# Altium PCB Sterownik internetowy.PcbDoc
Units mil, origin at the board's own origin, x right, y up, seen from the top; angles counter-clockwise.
Board outline 6000 x 4000 mil, 2 copper layers (Top Layer, Bottom Layer); 75 components, 94 nets, 398 pads, 73 vias.
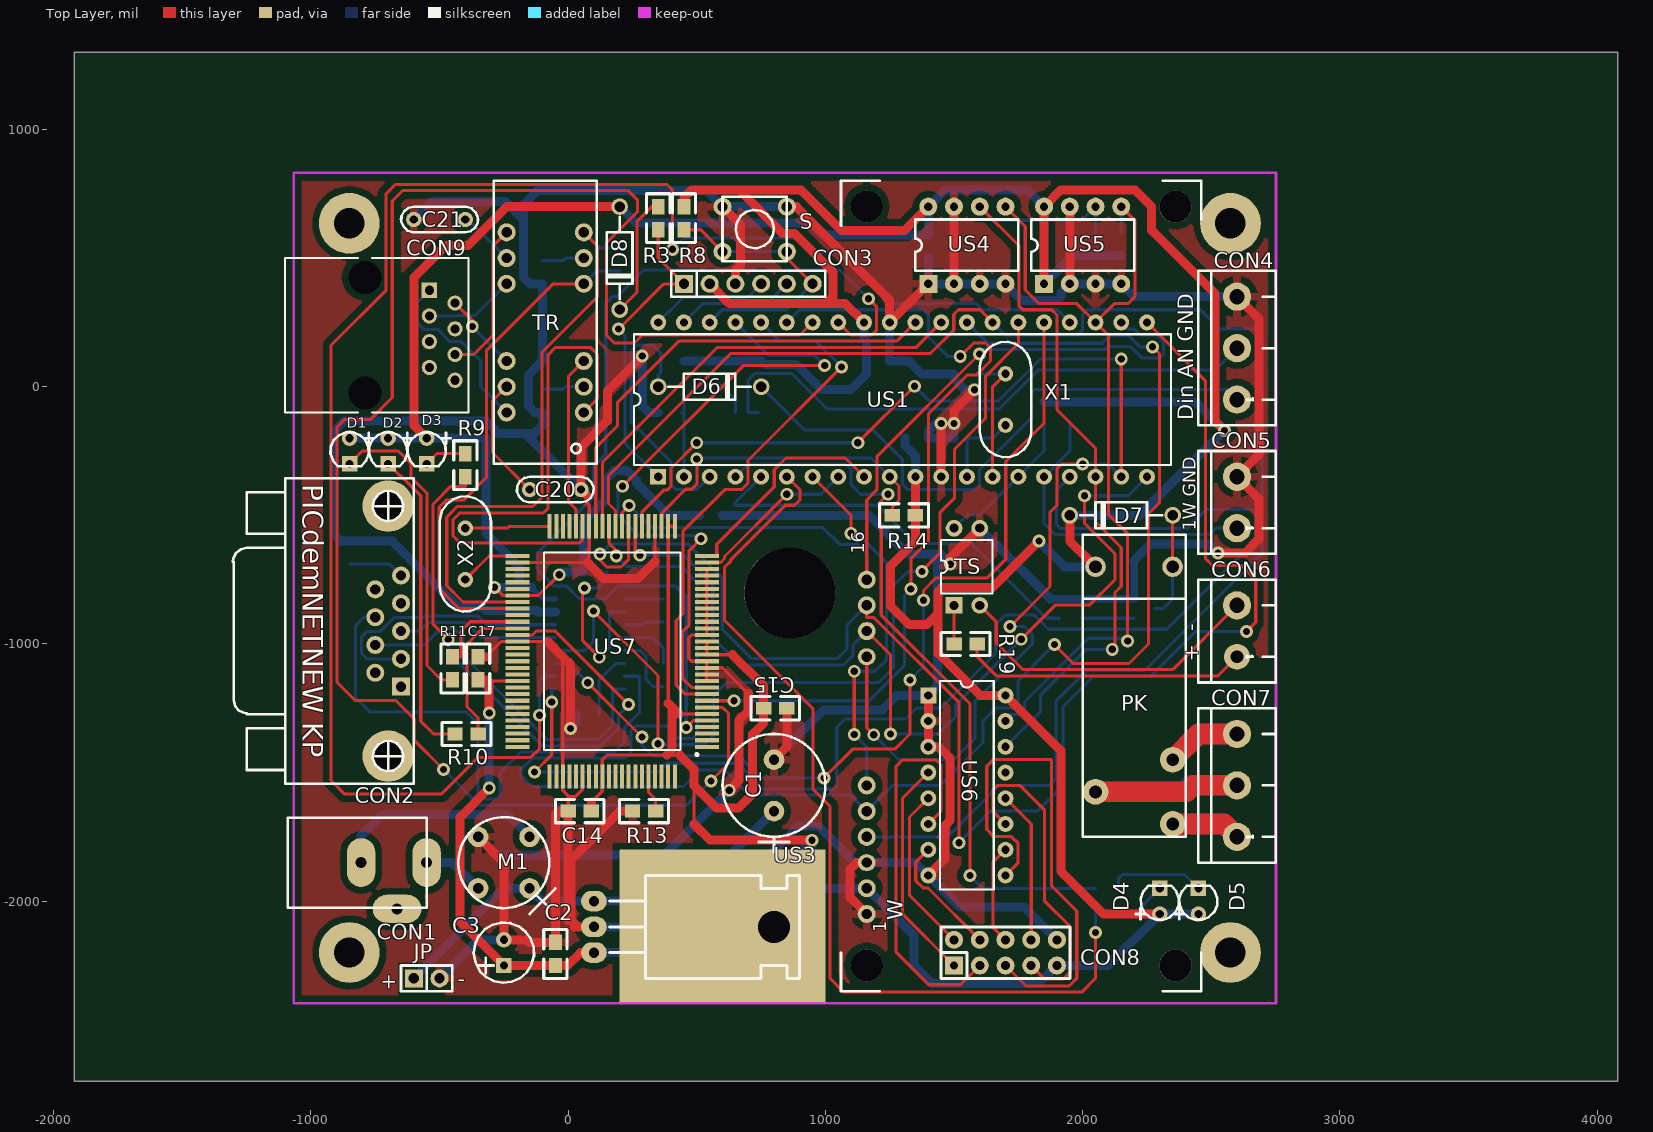
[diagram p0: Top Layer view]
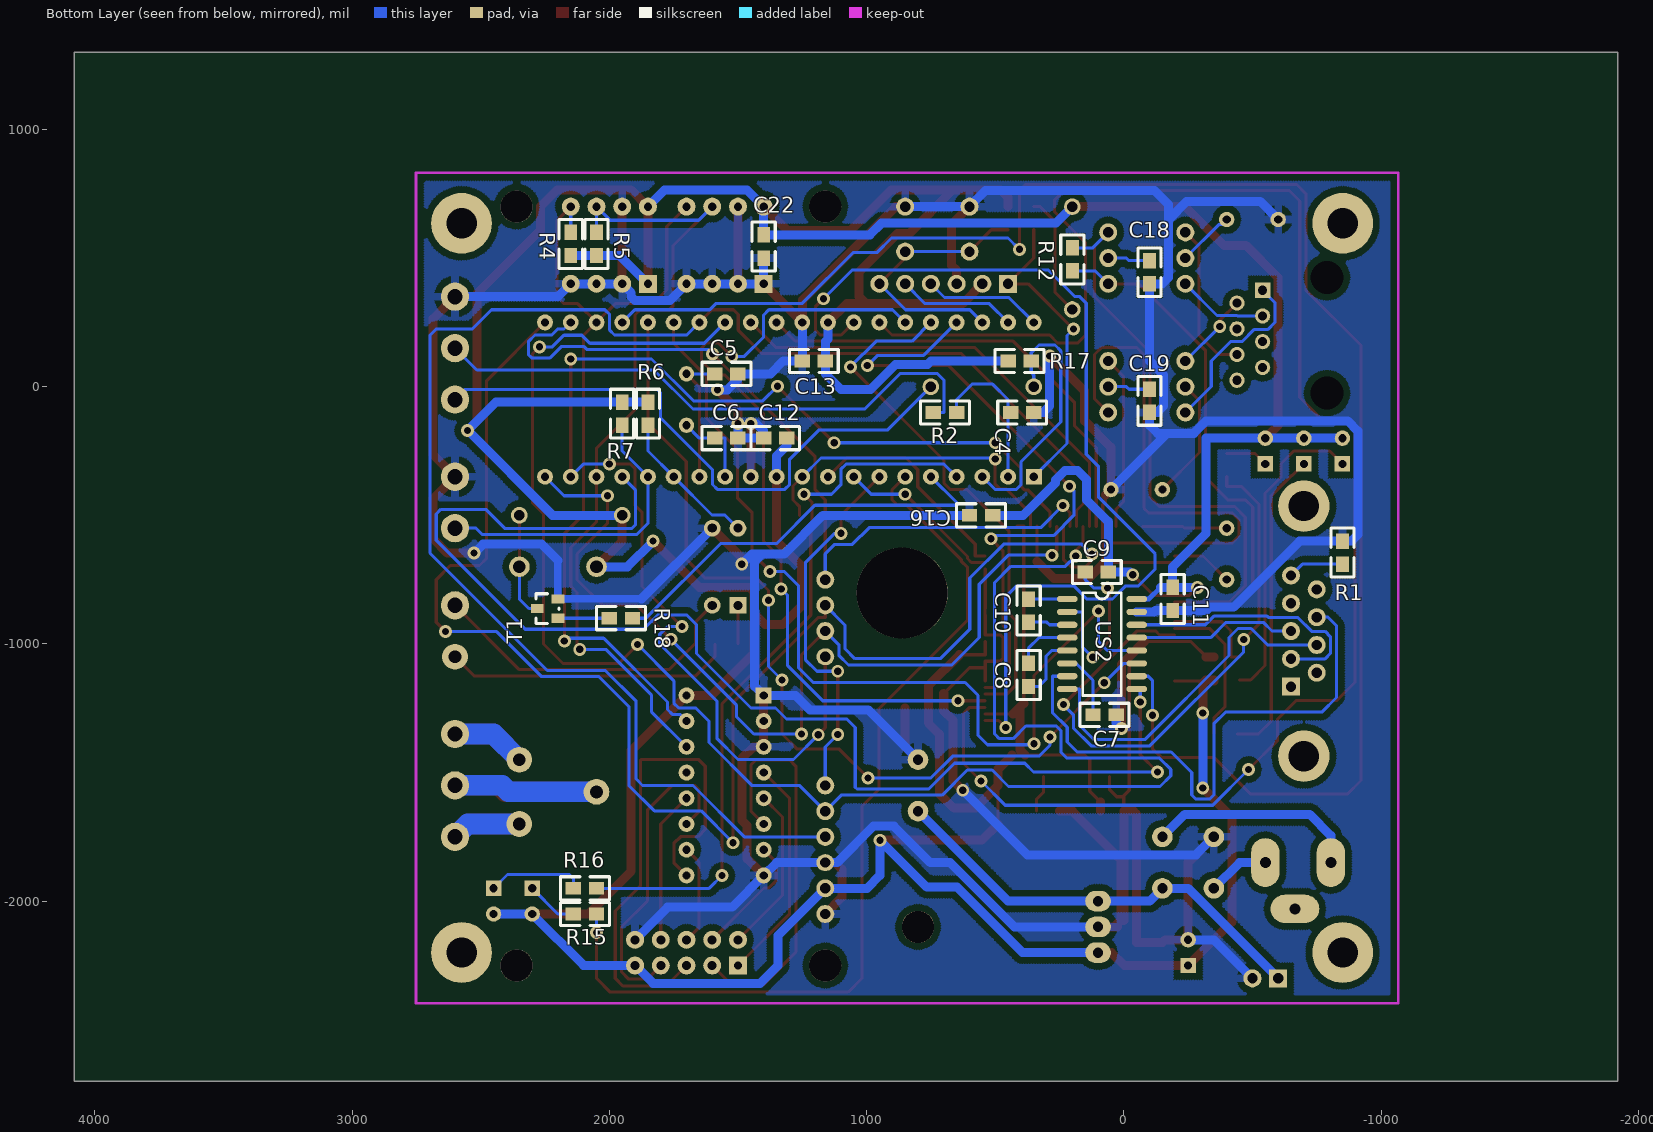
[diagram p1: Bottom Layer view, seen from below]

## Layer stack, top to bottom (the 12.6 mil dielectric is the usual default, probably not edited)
Top Layer: signal copper 1.4
Dielectric: dielectric 12.6, FR-4, Dk 4.8
Bottom Layer: signal copper 1.4

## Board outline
-1920,-2700 4080,-2700 4080,1300 -1920,1300

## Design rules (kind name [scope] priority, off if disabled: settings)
Clearance Clearance_3 [All] p1: gap=25
Clearance Clearance_1 [InComponent('US7')] p2 off: gap=8
Clearance Clearance_2 [InComponent('PK')] p3 off: gap=30
Clearance [All] p4 off: gap=12
ComponentClearance [All] p1: gap=10 collisioncheckmode=3 verticalgap=10
PolygonConnect [All] p1: connectstyle=Relief reliefconductorwidth=30 reliefentries=4 polygonreliefangle="90 Angle"
RoutingVias [All] p1: holewidth=28 width=50 viastyle="Through Hole" minholewidth=28 minwidth=50 maxholewidth=28 maxwidth=50
SMDNeckDown [All] p1: percent=80.000
SolderMaskExpansion [All] p1: expansion=4
TestPointUsage [All] p1: valid=0 allowmultiple=FALSE
Testpoint [All] p1: side=15 testpointundercomponent=TRUE minsize=40 maxsize=100 preferedsize=60 minholesize=0 maxholesize=40 preferedholesize=32 testpointgrid=1 style=1023 order=0123456789
Width Width_2 [InNet('NetCON7_3') Or InNet('NetCON7_1') Or InNet('NetCON7_2')] p1: maxlimit=90 minlimit=60 preferedwidth=80
Width Width_1 [InNet('VCC') Or InNet('GND')Or InNet('NetC1_1')Or InNet('NetCON1_1')Or InNet('NetCON1_2')] p2: maxlimit=35 minlimit=25 preferedwidth=35
Width [All] p3: maxlimit=12 minlimit=12 preferedwidth=12
17 further rules are at their usual default settings.

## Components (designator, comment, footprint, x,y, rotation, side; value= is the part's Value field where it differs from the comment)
C1 "470uF" CE10/5 800,-1650 r90 top
C2 "100nF" 0805 -50,-2250 r90 top
C3 "220uF" elektr1 -250,-2250 r180 top
C4 "100n" 0805 350,-100 r0 bottom
C5 "15p" 0805 1500,50 r0 bottom
C6 "15p" 0805 1500,-200 r0 bottom
C7 "1u" 0805 119.84,-1275.51 r180 bottom
C8 "1u" 0805 369.84,-1075.51 r270 bottom
C9 "1u" 0805 60,-720 r0 bottom
C10 "1u" 0805 369.84,-825.51 r270 bottom
C11 "1u" 0805 -190,-870 r90 bottom
C12 "100n" 0805 1400,-200 r180 bottom
C13 "100n" 0805 1250,100 r180 bottom
C14 "100N" 0805 0,-1650 r0 top
C15 "100N" 0805 850,-1250 r180 top
C16 "100N" 0805 600,-500 r180 bottom
C17 "100N" 0805 -350,-1050 r270 top
C18 "100N" 0805 -100,400 r90 bottom
C19 "100N" 0805 -100,-100 r90 bottom
C20 "100N" cap1 -50,-400 r180 top
C21 "100N" cap1 -500,650 r0 top
C22 "100N" 0805 1400,500 r90 bottom
CON1 "CON2" GNIAZDO-Z1 -550,-1850 r180 top
CON2 "DB9_zenskie" DB9Z -700,-950 r180 top
CON3 "Header 6" SIP-6 450,400 r0 top
CON4 "Header 3" con3-5 2600,150 r90 top locked
CON5 "Header 2" CON2-5#1 2600,-450 r270 top locked
CON6 "Header 2" CON2-5#2 2600,-950 r270 top locked
CON7 "Header 3" con3-5 2600,-1550 r90 top locked
CON8 "Header 10" IDC-10 1100,-1650 r0 top
CON9 "Header 8" JACK1.27-2H8B -1100,200 r270 top
D1 "LED0" led3 -850,-300 r0 top
D2 "LED0" led3 -700,-300 r0 top
D3 "LED0" led3 -550,-300 r0 top
D4 "LED0" led3 2300,-1950 r180 top
D5 "LED0" led3 2450,-1950 r180 top
D6 "BAT43" DIODa 550,0 r0 top
D7 "Diode 1N4007" DIODa 2150,-500 r180 top
D8 "Diode 1N4148" DIODa 200,500 r270 top
JP "CON2" sip2 -600,-2300 r0 top
M1 "" MOSTEK1 -350,-1750 r0 top
PK "RM96P-12" RM96P-12 2350,-700 r90 top
R1 "10" 0805 -850,-600 r270 bottom
R2 "2,2K" 0805 650,-100 r0 bottom
R3 "4,7K" 0805 350,700 r270 top
R4 "4,7K" 0805 2150,600 r270 bottom
R5 "4,7K" 0805 2050,600 r270 bottom
R6 "4,7K" 0805 1850,-150 r90 bottom
R7 "4,7K" 0805 1950,-150 r90 bottom
R8 "4,7K" 0805 450,700 r270 top
R9 "1K" 0805 -400,-350 r90 top
R10 "1K" 0805 -350,-1350 r180 top
R11 "1K" 0805 -450,-1050 r270 top
R12 "200R" 0805 200,450 r90 bottom
R13 "22K" 0805 250,-1650 r0 top
R14 "20K" 0805 1350,-500 r180 top
R15 "330R" 0805 2050,-2050 r0 bottom
R16 "330R" 0805 2050,-1950 r0 bottom
R17 "4,7K" 0805 450,100 r180 bottom
R18 "4,7K" 0805 2000,-900 r180 bottom
R19 "1K" 0805 1500,-1000 r0 top
S "SW-PB" key1 600,700 r270 top
T1 "NPN" sot-23 2200,-900 r90 bottom
TR "FL1012" fl1012 -289.37,-300 r90 top
TS "PC817" dip-4 1550,-700 r0 top
US1 "PIC18F452-E/P" PDIP600-40 1300,-50 r0 top
US2 "MAX232" so16 219.84,-825.51 r270 bottom
US3 "7805" TO-220 100,-2000 r270 top
US4 "AT24C256" DIP8 1400,400 r90 top
US5 "AT24C256" DIP8 1850,400 r90 top
US6 "PCF8574A" DIP-16 1550,-1550 r270 top
US7 "RTL8019AS" RTL8019 500,-1400 r90 top locked
W "LCD 16*1" LCDxxx 1160.63,-2050 r90 top locked
X1 "XTAL" XTAL 1700,-50 r270 top
X2 "20MHZ" XTAL -400,-650 r270 top

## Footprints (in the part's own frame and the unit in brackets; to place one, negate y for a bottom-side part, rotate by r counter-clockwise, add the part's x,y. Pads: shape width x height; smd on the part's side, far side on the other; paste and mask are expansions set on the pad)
0805 [mil]
  rect 60x50 smd: 1(0,0) 2(90,0)
  silkscreen extent -50,-45 140,45
cap1 [mil]
  round 60 hole 32: 1(-100,0) 2(100,0)
  silkscreen extent -150,-50 150,50
CE10/5 [mil]
  round 80 hole 40: 1(0,0) 2(200,0)
  silkscreen extent -160,-200 300,200
CON2-5#1 [mil]
  round 110 hole 60: 1(100,0) 2(-100,0)
  silkscreen extent -200,-150 200,150
CON2-5#2 [mil]
  round 100 hole 50: 1(100,0)
  round 110 hole 60: 2(-100,0)
  silkscreen extent -200,-150 200,150
con3-5 [mil]
  round 110 hole 60: 1(-200,0) 2(0,0) 3(200,0)
  silkscreen extent -300,-150 300,150
DB9Z [mil]
  rect 70x70 hole 40: 1(-50,216)
  round 70 hole 40: 2(-50,108) 3(-50,0) 4(-50,-108) 5(-50,-216) 6(50,162) 7(50,54) 8(50,-54) 9(50,-162)
  round 200 hole 118.11: 23(0,486) 26(0,-486)
  Bottom Layer lines w10: -52,221 -55,221
  silkscreen extent -100,-594 604,594
DIODa [mil]
  round 65 hole 40: 1(-200,0) 2(200,0)
  silkscreen extent -160,-50 160,50
DIP8 [mil]
  rect 70x70 hole 32: 1(0,0)
  round 70 hole 32: 2(0,-100) 3(0,-200) 4(0,-300) 5(300,-300) 6(300,-200) 7(300,-100) 8(300,0)
  silkscreen extent 50,-350 250,50
dip-4 [mil] "DIP; 4 Leads; Row Spacing 7.62 mm; Pitch 2.54 mm"
  rect 65x65 hole 35.43: 1(-50,-150)
  round 65 hole 35.43: 2(50,-150) 3(50,150) 4(-50,150)
  silkscreen extent -100,-104 100,104
DIP-16 [mil] "DIP; 16 Leads; Row Spacing 7.62 mm; Pitch 2.54 mm"
  rect 62x62 hole 32: 1(-350,-150)
  round 62 hole 32: 2(-250,-150) 3(-150,-150) 4(-50,-150) 5(50,-150) 6(150,-150) 7(250,-150) 8(350,-150) 9(350,150) 10(250,150) 11(150,150) 12(50,150) 13(-50,150) 14(-150,150) 15(-250,150) 16(-350,150)
  silkscreen extent -406,-104 406,104
elektr1 [mil]
  rect 60x60 hole 32: 1(0,0)
  round 60 hole 32: 2(0,-100)
  silkscreen extent -117,-167 118,67
fl1012 [mil]
  round 70 hole 40: 1(200,-350) 2(300,-350) 3(400,-350) 6(700,-350) 7(800,-350) 8(900,-350) 9(900,-50) 10(800,-50) 11(700,-50) 14(400,-50) 15(300,-50) 16(200,-50)
  silkscreen extent 0,-400 1100,0
GNIAZDO-Z1 [mil]
  oval 110x190 hole 43: 1(0,0) 2(255,0)
  oval 190x110 hole 43: 3(115,180)
  silkscreen extent 0,-175 540,175
IDC-10 [mil]
  rect 70x70 hole 32: 1(400,-600)
  round 70 hole 35: 2(400,-500) 3(500,-600) 4(500,-500) 5(600,-600) 6(600,-500) 7(700,-600) 8(700,-500) 9(800,-600) 10(800,-500)
  silkscreen extent 350,-650 850,-450
JACK1.27-2H8B [mm] "Connector; PCB Jack, Thru-Hole; 1-Port, 8 Positions, 8 Loaded; Unshielded without Lightpipes; Right Angle"
  rect 1.5x1.5 hole 0.9: 1(-4.445,14.23)
  round 1.5 hole 0.9: 2(-3.175,16.77) 3(-1.905,14.23) 4(-0.635,16.77) 5(0.635,14.23) 6(1.905,16.77) 7(3.175,14.23) 8(4.445,16.77)
  round 2.95 hole 3.25 unplated: MH1(-5.715,7.88) MH2(5.715,7.88)
  silkscreen extent -7.62,0 7.62,18.1
key1 [mil]
  round 70 hole 40: 1(0,250) 1(0,0) 2(175,250) 2(175,0)
  silkscreen extent -38,0 212,250
LCDxxx [mil]
  round 70 hole 40: 1(0,0) 2(100,0) 4(300,0) 5(400,0) 6(500,0) 12(1100,0) 13(1200,0) 14(1300,0)
  oval 65x70 hole 40: 3(200,0) 11(1000,0)
  round 125 hole 125: ""(-200,0) ""(-200,-1200) ""(2750,-1200) ""(2750,0)
  silkscreen extent -300,-1300 2850,100
led3 [mil]
  rect 60x60 hole 32: 1(0,0)
  round 60 hole 32: 2(0,100)
  silkscreen extent -74,-10 93,123
MOSTEK1 [mil]
  round 80 hole 40: 1(200,0) 2(200,-200) 3(0,-200) 4(0,0)
  silkscreen extent -77,-300 300,77
PDIP600-40 [mil] "DIP, Plastic; 40 Leads; Row Spacing 15.24 mm; Pitch 2.54 mm"
  rect 62x62 hole 32: 1(-950,-300)
  round 62 hole 32: 2(-850,-300) 3(-750,-300) 4(-650,-300) 5(-550,-300) 6(-450,-300) 7(-350,-300) 8(-250,-300) 9(-150,-300) 10(-50,-300) 11(50,-300) 12(150,-300) 13(250,-300) 14(350,-300) 15(450,-300) 16(550,-300) 17(650,-300) 18(750,-300) 19(850,-300) 20(950,-300) 21(950,300) 22(850,300) 23(750,300) 24(650,300) 25(550,300) 26(450,300) 27(350,300) 28(250,300) 29(150,300) 30(50,300) 31(-50,300) 32(-150,300) 33(-250,300) 34(-350,300) 35(-450,300) 36(-550,300) 37(-650,300) 38(-750,300) 39(-850,300) 40(-950,300)
  silkscreen extent -1043,-254 1043,254
RM96P-12 [mil]
  round 80 hole 50: 1(0,0) 2(0,300)
  round 100 hole 50: 3(-750,0) 4(-875,300) 5(-1000,0)
  silkscreen extent -1050,-50 125,350
RTL8019 [mm]
  rect 0.4x2.4 smd: 1(0,-1) 2(0.65,-1) 3(1.3,-1) 4(1.95,-1) 5(2.6,-1) 6(3.25,-1) 7(3.9,-1) 8(4.55,-1) 9(5.2,-1) 10(5.85,-1) 11(6.5,-1) 12(7.15,-1) 13(7.8,-1) 14(8.45,-1) 15(9.1,-1) 16(9.75,-1) 17(10.4,-1) 18(11.05,-1) 19(11.7,-1) 20(12.35,-1) 21(13,-1) 22(13.65,-1) 23(14.3,-1) 24(14.95,-1) 25(15.6,-1) 26(16.25,-1) 27(16.9,-1) 28(17.55,-1) 29(18.2,-1) 30(18.85,-1) 51(18.85,17.7) 52(18.2,17.7) 53(17.55,17.7) 54(16.9,17.7) 55(16.25,17.7) 56(15.6,17.7) 57(14.95,17.7) 58(14.3,17.7) 59(13.65,17.7) 60(13,17.7) 61(12.35,17.7) 62(11.7,17.7) 63(11.05,17.7) 64(10.4,17.7) 65(9.75,17.7) 66(9.1,17.7) 67(8.45,17.7) 68(7.8,17.7) 69(7.15,17.7) 70(6.5,17.7) 71(5.85,17.7) 72(5.2,17.7) 73(4.55,17.7) 74(3.9,17.7) 75(3.25,17.7) 76(2.6,17.7) 77(1.95,17.7) 78(1.3,17.7) 79(0.65,17.7) 80(0,17.7)
  rect 2.4x0.4 smd: 31(21.775,2.175) 32(21.775,2.825) 33(21.775,3.475) 34(21.775,4.125) 35(21.775,4.775) 36(21.775,5.425) 37(21.775,6.075) 38(21.775,6.725) 39(21.775,7.375) 40(21.775,8.025) 41(21.775,8.675) 42(21.775,9.325) 43(21.775,9.975) 44(21.775,10.625) 45(21.775,11.275) 46(21.775,11.925) 47(21.775,12.575) 48(21.775,13.225) 49(21.775,13.875) 50(21.775,14.525) 81(-2.925,14.525) 82(-2.925,13.875) 83(-2.925,13.225) 84(-2.925,12.575) 85(-2.925,11.925) 86(-2.925,11.275) 87(-2.925,10.625) 88(-2.925,9.975) 89(-2.925,9.325) 90(-2.925,8.675) 91(-2.925,8.025) 92(-2.925,7.375) 93(-2.925,6.725) 94(-2.925,6.075) 95(-2.925,5.425) 96(-2.925,4.775) 97(-2.925,4.125) 98(-2.925,3.475) 99(-2.925,2.825) 100(-2.925,2.175)
  silkscreen extent -0.89,-0.13 19.18,15.1
sip2 [mil]
  rect 70x70 hole 40: 1(0,0)
  round 70 hole 40: 2(100,0)
  silkscreen extent -50,-50 150,50
SIP-6 [mil]
  rect 70x70 hole 40: 1(0,0)
  round 70 hole 40: 2(100,0) 3(200,0) 4(300,0) 5(400,0) 6(500,0)
  silkscreen extent -50,-50 550,50
so16 [mil]
  oval 24x80 smd: 1(0,0) 2(50,0) 3(100,0) 4(150,0) 5(200,0) 6(250,0) 7(300,0) 8(350,0) 9(350,270) 10(300,270) 11(250,270) 12(200,270) 13(150,270) 14(100,270) 15(50,270) 16(0,270)
  silkscreen extent -25,60 375,210
sot-23 [mil]
  rect 36x50 smd: 1(0,0) 2(75,0) 3(38,80)
  silkscreen extent -20,-5 95,85
TO-220 [mil]
  oval 80x100 hole 40: 1(0,0) 2(100,0) 3(200,0)
  round 125 hole 125: ""(100,700)
  silkscreen extent -100,60 300,800
XTAL [mil]
  round 60 hole 32: 1(-100,0) 2(100,0)
  silkscreen extent -224,-100 224,100

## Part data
C1 C3: library part ELECTRO1, "Electrolytic Capacitor"
C2 C4 C7 C8 C9 C10 C11: library part CAP, "Capacitor"
C5 C6 C12 C13 C14 C15 C16 C17 C18 C19 C20 C21 C22: library part Cap, "Capacitor"
CON1: "Connector"
CON2: library part DB9
CON3: "Header, 6-Pin"
CON4: "Header, 3-Pin"
CON5: library part "Header 3", "Header, 3-Pin"
CON6: library part "Header 10", "Header, 10-Pin"
CON7: library part "Header 8", "Header, 8-Pin"
CON8: "Header, 10-Pin"
CON9: "Header, 8-Pin"
D1 D2 D3 D4 D5: "Typical INFRARED GaAs LED"
D6 D8: library part "Diode 1N4007", "1 Amp General Purpose Rectifier"
D7: "1 Amp General Purpose Rectifier"
M1: library part BRIDGE1, "Diode Bridge"
R1 R2 R3 R4 R5 R6 R7 R8 R9 R10 R11 R12 R13 R14 R15 R16 R17 R18 R19: library part Res2, "Resistor"
S: "Switch"
T1: "NPN Bipolar Transistor"
US1: "High Performance, Enhanced FLASH Microcontroller with 10-Bit A/D, 32K FLASH, 40-Pin PDIP, Standard Volt Range, Extended Temperature"
US3: library part STAB1
US4: library part AT24C64
US5: library part PCF8574A
US7: library part RTL8019
X1: "Crystal Oscillator"
X2: library part XTAL, "Crystal Oscillator"

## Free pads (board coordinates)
  round 236.22 hole 118.11: 0(-850.79,635.04) 1(-850.79,-2199.61) 2(2574.41,-2199.61) 3(2574.41,635.04)
  round 354.33 hole 354.33: 4(861.81,-801.97)
  rect 800x600 smd: 5(600,-2100)

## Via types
v1: diameter 50, hole 28, Top Layer to Bottom Layer, 73 vias

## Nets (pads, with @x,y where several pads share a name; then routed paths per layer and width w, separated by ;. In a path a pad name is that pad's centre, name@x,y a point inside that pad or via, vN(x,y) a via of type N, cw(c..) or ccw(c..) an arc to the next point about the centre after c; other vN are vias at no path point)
A0: US1.33 US7.5 | length 3845.4
  Top Layer w12: v1(459,-1325) 486.36,-1297.64 US7.5 ; US1.33 1099,201 1180,201 1199,220 1199,310.5 v1(1167.5,342)
  Bottom Layer w12: v1(459,-1325) 459,-817 416,-774 195.01,-774 144.01,-825 44.01,-825 -6.99,-774 -57,-774 -122,-709 -122,-650 98,-430 98,-311 146,-263 146,325 171,350 190,350 293,453 1056.5,453 v1(1167.5,342)
A1: US1.34 US7.7 | length 6549.4
  Top Layer w12: v1(-485,-1488) -598,-1375 -598,-1292 -670,-1220 -828,-1220 -898,-1150 -898,-156 -870,-128 -770,-128 -683.79,-41.79 -683.79,722.21 -644,762 233,762 270,725 270,681 149,560 149,200 178.9,170.1 257.5,170.1 288.4,201 901,201 US1.34 ; US7.7 599.46,-1246.46 623,-1270 623,-1465 v1(555,-1533)
  Bottom Layer w12: v1(-485,-1488) -346,-1627 461,-1627 v1(555,-1533)
A2: US1.35 US7.8 | length 3185.8
  Top Layer w12: US7.8 v1(644.11,-1220.87) ; v1(1332,-787) 1332,-669 1401,-600 1401,-105.05 1552.18,46.13 1588.13,46.13 1642,100 1642,150 1622,170 1576,170 v1(1524,118)
  Bottom Layer w12: v1(644.11,-1220.87) 1170.42,-1220.87 1307,-1084.29 1307,-812 v1(1332,-787) ; US1.35 899,299 1380,299 1401,278 1401,192 1475,118 v1(1524,118)
A3: US1.36 US7.9 | length 2060.5
  Top Layer w12: US7.9 455,-1195.28 420,-1160.28 420,-909 446,-883 446,-562.5 608.5,-400 674,-400 699,-375 699,-287 v1(1063,77)
  Bottom Layer w12: US1.36 823,177 963,177 v1(1063,77)
A4: US1.37 US7.10 | length 2560.1
  Top Layer w12: v1(211,-387) 680,82 v1(997,82) ; v1(516.5,-591) 470,-637.5 470,-927 444,-953 444,-1133.68 480,-1169.68 US7.10
  Bottom Layer w12: v1(211,-387) 194,-404 194,-500 273,-579 504.5,-579 v1(516.5,-591) ; US1.37 778,122 957,122 v1(997,82)
CTS: US1.24 US2.10 | length 6674
  Top Layer w12: v1(-111,-1277) -111,-1407 -145,-1441 -350,-1441 -492,-1583 -870,-1583 -922,-1531 -922,160.79 -707.79,375 -707.79,750 -671.79,786 384,786 406,764 v1(406,534)
  Bottom Layer w12: v1(-111,-1277) -111,-1141.51 -95,-1125.51 US2.10 ; v1(406,534) 450,578 903,578 960,521 1053,521 1250,324 1585,324 1610,299 1901,299 US1.24
GND: C1.2 C2.2 C3.2 C4.1 C5.1 C6.1 C7.2 C11.1 C12.1 C13.1 C14.1 C15.1 C16.1 C17.1 C18.1 C19.1 C20.1 C21.1 C22.1 CON3.3 CON4.3 CON5.2 CON8.10 JP.2 M1.4 R1.1 R13.1 S.1 T1.2 TS.3 US1.12 US1.31 US2.15 US3.2 US4.1 US4.2 US4.3 US4.4 US4.7 US5.2 US5.3 US5.4 US5.7 US6.1 US6.2 US6.3 US6.8 US7.11 US7.12 US7.13 US7.14 US7.18 US7.19 US7.20 US7.21 US7.22 US7.23 US7.24 US7.25 US7.26 US7.27 US7.28 US7.34 US7.44 US7.52 US7.64 US7.83 US7.86 W.1 W.3 | length 26011.5
  Top Layer w12.6: -320.45,-1050 -261,-990.55 US7.64 -80.12,-990.55 ; US7.52 75.46,-683.46 ; -20.67,-1050 -20.67,-1329 US7.83 -20.67,-1568.66 0,-1589.33 ; C14.1 0,-1589.33 ; US7.86 56.1,-1565.4 27.17,-1594.33 5,-1594.33 0,-1589.33 ; 71.69,-421.69 71.69,-448.35 81.69,-458.35 US7.44 81.69,-632 80,-633.69 80,-688 ; 337.6,-679.4 US7.34 ; US7.11 539,-1144.09 US7.12@539,-1118.5 ; US7.12 US7.12@539,-1118.5 ; US7.14 US7.14@539,-1067.32 ; US7.18 US7.18@539,-964.96 ; US7.19 US7.19@539,-939.37 ; US7.20 US7.20@539,-913.78 ; US7.23 US7.23@539,-837.01 ; US7.24 US7.24@539,-811.42 ; US7.25 US7.25@539,-785.83 ; US7.26 US7.26@539,-760.24 ; US7.27 US7.27@539,-734.65 ; US7.28 539,-709.06 US7.27@539,-734.65 ; 700,-1192.91 600,-1092.91 US7.13 US7.13@539,-1092.91 ; US7.12@539,-1118.5 US7.13@539,-1092.91 ; US7.13@539,-1092.91 US7.14@539,-1067.32 ; US7.14@539,-1067.32 480,-1067.32 468.3,-1055.62 468.3,-976.66 480,-964.96 US7.18@539,-964.96 ; US7.18@539,-964.96 US7.19@539,-939.37 ; US7.19@539,-939.37 US7.20@539,-913.78 ; US7.20@539,-913.78 539,-888.19 US7.21 US7.22 539,-862.6 US7.23@539,-837.01 ; US7.23@539,-837.01 US7.24@539,-811.42 ; US7.24@539,-811.42 US7.25@539,-785.83 ; US7.25@539,-785.83 US7.26@539,-760.24 ; US7.26@539,-760.24 US7.27@539,-734.65
  Top Layer w35: M1.4 -250,-1850 C3.2 -160,-2150 -150,-2160 C2.2 -50,-1662.5 -37.5,-1650 C14.1 0,-2075 11,-2075 ; C17.1 -320.45,-1050 ; -80.12,-990.55 -20.67,-1050 9,-1079.67 v1(9,-1329) ; 71.69,-421.69 C20.1 50,-235 152,-133 152,-17 v1(288,119) ; 75.46,-683.46 80,-688 138,-746 271,-746 337.6,-679.4 ; US3.2 25,-2100 30.5,-2094.5 11,-2075 ; R13.1 200,-1650 11,-1839 11,-2075 ; S.1@600,700 670,630 670,472 650,452 CON3.3 ; v1(626,-1569) 664,-1531 664,-1297.42 700,-1261.42 700,-1192.91 ; C1.2 850,-1400 C15.1 ; S.1@850,700 887.01,700 1250,337.01 US1.31 US4.1 ; W.1 1096,-1985.37 1096,-1875 1121,-1850 W.3 ; US6.8 1464.5,-1835.5 1464.5,-1706.12 1484.5,-1686.12 1484.5,-1445 1439.5,-1400 US6.3 US6.2 US6.1 ; US1.12 v1(1450,-143) ; v1(1485.05,-689.95) 1485.05,-664.95 TS.3 ; v1(1500,-143) 1500,-92 v1(1580,-12) ; US4.2 US4.7 ; US5.2 US5.7 ; v1(2526,-647) 2630,-647 2685,-592 2685,-435 CON5.2 2685,-265 2685,265 CON4.3
  Bottom Layer w28.8: 1875,-825 T1.2 2200,-675
  Bottom Layer w35: C21.1 -530,720 -244,720 -174,650 ; JP.2 -350,-2150 C3.2 ; M1.4 -280,-1820 375,-1820 v1(626,-1569) ; US2.15 -117.49,-875.51 -123,-870 C11.1 -321,-870 -334.5,-856.5 -427,-856.5 -683.5,-600 R1.1 -885,-600 -910,-575 -910,-173 -870,-133 -320,-133 -272,-181 -169,-181 ; v1(9,-1329) 29.84,-1308.16 C7.2 ; C20.1 -169,-181 ; US3.2 425,-2100 675,-1850 752,-1850 893.5,-1708.5 973.5,-1708.5 1115,-1850 W.3 1350,-1850 US6.8 1523,-2023 1773,-2023 CON8.10 ; v1(288,119) 288,-75 313,-100 C4.1 ; C16.1 1169.5,-500 1320.5,-651 1407.11,-651 ; C1.2 993.5,-1256.5 1220.12,-1256.5 1276.62,-1200 US6.1 1435.5,-1164.5 1435.5,-679.39 1407.11,-651 ; S.1@850,700 600,700 538,762 -120,762 -174,708 -174,650 ; US1.31 C13.1 1323,100 1373,50 C5.1 1500,29 1541,-12 v1(1580,-12) ; C22.1 US4.1 US4.2 US4.3 US4.4 1765,335 1900,335 1915,350 1915,365 US5.2 US5.3 US5.4 2200,350 CON4.3 ; v1(1450,-143) 1430,-143 1400,-173 C12.1 C6.1 v1(1500,-143) ; v1(1485.05,-689.95) 1446.11,-651 1407.11,-651 ; TS.3 1875,-825 ; 2200,-675 2263,-612 2491,-612 v1(2526,-647) ; -174,650 -174,425 -149,400 C18.1 -100,100 -155,45 -155,-75 -130,-100 C19.1 -100,-150 -131,-181 -169,-181
MCLR: CON3.1 R3.2 US1.1 | length 1216.1
  Top Layer w12: v1(196,224) 372,400 CON3.1 350,500 R3.2
  Bottom Layer w12: v1(196,224) 221,199 221,-221 US1.1
NetC1_1: C1.1 JP.1 M1.2 US3.1 | length 1710.7
  Bottom Layer w35: JP.1 -250,-1950 M1.2 -100,-2000 US3.1 450,-2000 C1.1
NetC4_2: C4.2 R2.1 US1.2 | length 609.7
  Bottom Layer w12: C4.2 C4.2@450,-100 ; US1.2 C4.2@450,-100 ; R2.1 650,-50 590,10 550,10 510,10 450,-50 C4.2@450,-100
NetC5_2: C5.2 US1.14 X1.1 | length 530.7
  Top Layer w12: US1.14 1650,0 X1.1
  Bottom Layer w12: C5.2 X1.1
NetC6_2: C6.2 US1.13 X1.2 | length 320.7
  Bottom Layer w12: US1.13 1550,-200 C6.2 1650,-200 X1.2
NetC7_1: C7.1 US2.6 | length 261.3
  Bottom Layer w12: C7.1 119.84,-1141.51 185.84,-1075.51 US2.6
NetC8_1: C8.1 US2.4 | length 226.7
  Bottom Layer w12: US2.4 330,-975.51 369.84,-1015.35 C8.1
NetC8_2: C8.2 US2.5 | length 260.7
  Bottom Layer w12: US2.5 280,-1025.51 303,-1048.51 303,-1138.51 330,-1165.51 C8.2
NetC9_2: C9.2 US2.2 | length 682.8
  Top Layer w12: v1(63,-782) 55,-790 55,-986 v1(121,-1052)
  Bottom Layer w12: v1(63,-782) 118,-782 150,-750 C9.2 ; v1(121,-1052) 161,-1012 161,-875.51 US2.2
NetC10_1: C10.1 US2.1 | length 150
  Bottom Layer w12: US2.1 C10.1
NetC10_2: C10.2 US2.3 | length 154.1
  Bottom Layer w12: US2.3 289,-925.51 299,-915.51 C10.2
NetC18_2: C18.2 TR.7 | length 164.8
  Bottom Layer w12: C18.2 -20,490 -10,500 TR.7
NetC19_2: C19.2 TR.2 | length 164.8
  Bottom Layer w12: C19.2 -20,-10 -10,0 TR.2
NetC20_2: C20.2 TR.15 | length 482.3
  Top Layer w12: TR.15 -294,-54.63 -294,-256 C20.2
NetC21_2: C21.2 TR.10 | length 233.9
  Bottom Layer w12: C21.2 -400,631 -370.37,631 TR.10
NetCON1_1: CON1.1 M1.3 | length 241.4
  Bottom Layer w35: CON1.1 -450,-1850 M1.3
NetCON1_2: CON1.2 M1.1 | length 830.4
  Bottom Layer w35: CON1.2 -805,-1745 -722.5,-1662.5 -237.5,-1662.5 M1.1
NetCON2_2: CON2.2 US2.14 | length 1027.1
  Bottom Layer w12: CON2.2 -782.5,-1058 -803,-1037.5 -803,-971.5 -782.5,-951 -730.05,-951 -676.05,-897 -562.13,-897 -557.13,-892 -350,-892 -316.49,-925.51 US2.14
NetCON2_3: CON2.3 US2.13 | length 638.6
  Bottom Layer w12: CON2.3 -576.14,-950 -542.14,-916 -397,-916 -337.49,-975.51 US2.13
NetCON2_5: CON2.5 R1.2 | length 218.2
  Bottom Layer w12: R1.2 -694,-690 CON2.5
NetCON2_7: CON2.7 US2.8 | length 1380
  Bottom Layer w12: CON2.7 -559,-1004 -495,-940 -444,-940 -409,-975 -409,-1045 -82,-1372 116,-1372 172,-1316 172,-1175.51 US2.8
NetCON2_8: CON2.8 US2.7 | length 2223.7
  Bottom Layer w12: CON2.8 -794,-896 -827,-929 -827,-1208 -770,-1265 -395,-1265 -350,-1310 -350,-1587.5 -334.5,-1603 -279.5,-1603 -264,-1587.5 -264,-1500 -184,-1420 180.92,-1420 220,-1380.92 220,-1324.22 278,-1266.22 278,-1125.51 US2.7
NetCON4_1: CON4.1 D6.2 | length 2340.2
  Bottom Layer w12: D6.2 917.6,-167.6 1184.6,-167.6 1299,-282 1299,-380.5 1317.5,-399 1580,-399 1599,-380 1599,-323 1800.43,-121.57 1800.43,-25 1814.89,-10.54 2560.54,-10.54 CON4.1
NetCON4_2: CON4.2 R2.2 | length 2233.1
  Bottom Layer w12: R2.2 699,-100 699,25 725,51 869,51 1007,-87 1675,-87 1827,65 2515,65 CON4.2
NetCON5_1: CON5.1 R7.1 US1.16 | length 1200.6
  Bottom Layer w12: R7.1 1950,-250 US1.16 1850,-531 1893.5,-574.5 2494,-574.5 2518.5,-550 CON5.1
NetCON6_1: CON6.1 R19.2 | length 1121.3
  Top Layer w12: R19.2 1590,-1050 1664,-1124 2526,-1124 CON6.1
NetCON6_2: CON6.2 TS.2 | length 1255.2
  Top Layer w12: TS.2 1664.26,-914.26 1664.26,-996.35 1767.9,-1100 2350,-1100 CON6.2
NetCON7_1: CON7.1 PK.5 | length 541.4
  Top Layer w80: PK.5 2550,-1700 CON7.1
  Bottom Layer w80: PK.5 2550,-1700 CON7.1
NetCON7_2: CON7.2 PK.4 | length 1120.7
  Top Layer w80: PK.4 2405,-1575 2430,-1550 CON7.2
  Bottom Layer w80: PK.4 2392,-1575 2417,-1550 CON7.2
NetCON7_3: CON7.3 PK.3 | length 582.8
  Top Layer w80: PK.3 2450,-1350 CON7.3
  Bottom Layer w80: PK.3 2450,-1350 CON7.3
NetCON8_1: CON8.1 US6.4 | length 875
  Top Layer w12: US6.4 1299.13,-1600.87 1299.13,-2049.13 CON8.1
NetCON8_2: CON8.2 US6.5 | length 651.9
  Top Layer w12: US6.5 1327,-1673 1327,-1977 CON8.2
NetCON8_3: CON8.3 US6.6 | length 1573.8
  Top Layer w12: US6.6 1449,-1651 1449,-1470 1430,-1451 1299,-1451 1275,-1475 1275,-2198 1402,-2325 1525,-2325 CON8.3
NetCON8_4: CON8.4 US6.7 | length 484.7
  Top Layer w12: US6.7 1351,-1849 1351,-1920.3 1379.7,-1949 1399,-1949 CON8.4
NetCON8_5: CON8.5 US6.9 | length 2009.6
  Top Layer w12: CON8.5 1779.46,-2329.46 1947.54,-2329.46 1977,-2300 1977,-2038 1879,-1940 1879,-1452 1877,-1450 1652,-1450 1627,-1475 1627,-1721 1655,-1749 1723,-1749 1749,-1775 1749,-1851 US6.9
NetCON8_6: CON8.6 US6.10 | length 390.6
  Top Layer w12: CON8.6 1651,-2101 1651,-1849 US6.10
NetCON8_7: CON8.7 US6.11 | length 1258
  Top Layer w12: US6.11 1651,-1651 1651,-1567.5 1667.5,-1551 1758,-1551 1851,-1644 1851,-1998 1953,-2100 1953,-2275 1925,-2303 1853,-2303 CON8.7
NetCON8_8: CON8.8 US6.12 | length 591.4
  Top Layer w12: US6.12 1800,-1700 CON8.8
NetCON9_1: CON9.1 TR.16 | length 696.8
  Bottom Layer w12: CON9.1 -588,326.76 -588,250 -561,223 -507.5,223 -459.5,175 -415,175 -340,100 -340,0.63 TR.16
NetCON9_2: CON9.2 TR.14 | length 308
  Top Layer w12: CON9.2 -373,258.24 v1(-373,233.63)
  Bottom Layer w12: v1(-373,233.63) TR.14
NetCON9_3: CON9.3 TR.11 | length 352.2
  Bottom Layer w12: CON9.3 -442,275 -440,277 -362.37,277 TR.11
NetCON9_6: CON9.6 TR.9 | length 600.6
  Top Layer w12: CON9.6 -367,125 -293,199 -293,546.37 TR.9
NetD1_2: D1.1 R11.2 | length 1212.2
  Top Layer w12: D1.1 -800,-250 -661.11,-250 -611.11,-300 -611.11,-352.07 -549.19,-413.99 -549.19,-1083.81 -493,-1140 R11.2
NetD2_2: D2.1 R10.2 | length 1208.1
  Top Layer w12: D2.1 -654,-346 -651.12,-346 -573.19,-423.93 -573.19,-1300 -523.19,-1350 R10.2
NetD3_2: D3.1 R9.2 | length 166.6
  Top Layer w12: D3.1 -510,-260 R9.2
NetD4_2: D4.1 R15.2 | length 201.4
  Bottom Layer w12: R15.2 2200,-2050 D4.1
NetD5_2: D5.1 R16.2 | length 377.6
  Bottom Layer w12: R16.2 2140,-1911 2155,-1896 2396,-1896 D5.1
NetD6_1: D6.1 R17.2 US1.3 | length 1035.6
  Bottom Layer w12: D6.1 350,45 360,55 R17.2 360,132 330,162 267.5,162 245,139.5 245,-137 400,-292 400,-381.5 417.5,-399 501,-399 US1.3
NetD7_1: D7.1 PK.1 T1.3 | length 410.3
  Top Layer w12: PK.1 D7.1
  Bottom Layer w12: T1.3 2313,-862 2350,-825 PK.1
NetD8_2: D8.2 R3.1 | length 476.9
  Top Layer w12: D8.2 268,368 268,643.15 324.85,700 R3.1
NetR6_1: R6.1 TS.4 US1.15 | length 574.3
  Bottom Layer w12: TS.4 1551,-499 1601,-499 US1.15 1850,-250 R6.1
NetR9_1: R9.1 US7.63 | length 2296.9
  Top Layer w12: v1(-466,-983) -525.19,-923.81 -525.19,-456.19 -456.5,-387.5 -400,-387.5 R9.1 ; US7.63 -138.96,-964.96 -123,-949 -52,-949 v1(235,-1236)
  Bottom Layer w12: v1(-466,-983) -466,-1031.23 -101.23,-1396 127,-1396 196,-1327 196,-1275 v1(235,-1236)
NetR10_1: R10.1 US7.62 | length 589.1
  Top Layer w12: R10.1 -350,-1288 -393,-1245 -393,-1000 -332.37,-939.37 US7.62
NetR11_1: R11.1 US7.61 | length 368.2
  Top Layer w12: R11.1 -417,-1050 -417,-950 -380.78,-913.78 US7.61
NetR12_1: R12.1 TR.6 US7.59 | length 2024.3
  Top Layer w12: US7.59 -424.4,-862.6 -501.19,-785.81 -501.19,-467.97 -474.25,-441.03 -405.94,-441.03 -318,-353.09 -318,140 -58,400 TR.6
  Bottom Layer w12: TR.6 110.63,450 R12.1
NetR12_2: R12.2 TR.8 US7.58 | length 2275.9
  Top Layer w12: US7.58 -408.99,-837.01 -472,-774 -472,-507.09 -430.91,-466 -138,-466 -102,-430 -102,134 114,350 114,546.63 TR.8
  Bottom Layer w12: TR.8 120.63,540 R12.2
NetR13_2: R13.2 US7.96 | length 146.4
  Top Layer w12: US7.96 312.01,-1577 340,-1604.99 R13.2
NetR14_2: R14.2 US1.10 US7.33 | length 1289.9
  Top Layer w12: US7.33 363.19,-491.55 455.96,-398.78 480.35,-398.78 500,-379.13 v1(500,-281.51) ; US1.10 1286,-386 1286,-440.46 1260,-466.46 R14.2
  Bottom Layer w12: v1(500,-281.51) 504.51,-277 1177,-277 US1.10
NetR15_1: R15.1 US1.6 | length 3611
  Top Layer w12: US1.6 901,-401 901,-440 880,-461 843.26,-461 632,-672.26 632,-677.94 607,-702.94 607,-907 951,-1251 951,-1564 1018,-1631 1018,-2300 1071.46,-2353.46 1996.54,-2353.46 2050,-2300 v1(2050,-2122)
  Bottom Layer w12: v1(2050,-2122) R15.1
NetR16_1: R16.1 US1.4 | length 2845.7
  Top Layer w12: v1(1243,-418) 1212,-449 1212,-543 1217,-548 1217,-888 1562,-1233 v1(1562,-1900)
  Bottom Layer w12: US1.4 699,-301 1080,-301 1100,-321 1100,-381.5 1136.5,-418 v1(1243,-418) ; v1(1562,-1900) 1612,-1950 R16.1
NetR18_1: R18.1 T1.1 | length 200
  Bottom Layer w12: R18.1 T1.1
NetR18_2: R18.2 US1.5 | length 1597.1
  Bottom Layer w12: US1.5 648,-452 648,-461 1201,-461 1350,-610 1568,-610 1858,-900 R18.2
NetR19_1: R19.1 TS.1 | length 150
  Top Layer w12: R19.1 TS.1
NetTR_1: TR.1 US7.45 | length 2082.8
  Top Layer w12: US7.45 56.1,-594.4 42.5,-608 -420,-608 -448,-580 -448,-517.03 -421.99,-491.02 -97.02,-491.02 -78,-472 -78,124 -49,153 85.63,153 113.63,125 113.63,-47 TR.1
NetTR_3: TR.3 US7.46 | length 678.8
  Top Layer w12: US7.46 30.51,-476.51 2,-448 2,41.37 TR.3
NetUS1_7: US1.7 W.6 | length 1453.7
  Top Layer w12: US1.7 1099,-499 v1(1099,-570) ; v1(1112,-1352) v1(1112,-1106.03)
  Bottom Layer w12: v1(1099,-570) 1124,-570 1238,-684 1238,-1061 1192.97,-1106.03 v1(1112,-1106.03) ; v1(1112,-1352) 1160.63,-1400.63 W.6
NetUS1_8: US1.8 US7.29 | length 653.4
  Top Layer w12: US7.29 592.54,-683.46 608,-668 608,-660 v1(850,-418)
  Bottom Layer w12: v1(850,-418) 982,-418 US1.8
NetUS1_9: US1.9 US7.30 | length 863.9
  Top Layer w12: US7.30 577.59,-657.87 577.59,-612.3 801,-388.89 801,-323 847,-277 1077,-277 US1.9
NetUS1_19: US1.19 US7.36 W.11 | length 5055
  Top Layer w12: US7.36 286.42,-487.5 373.12,-400.8 386.7,-400.8 400,-387.5 400,-318 v1(500,-218) ; v1(1126,-218) v1(1346,2) ; W.11 1160.63,-1325.63 v1(1188,-1353) ; v1(1718,-932) 1873,-777 1873,-488 1901,-460 1901,-317.5 1917.5,-301 v1(2000,-301) ; US1.19 v1(2150,108)
  Bottom Layer w12: v1(500,-218) v1(1126,-218) ; v1(1188,-1353) 1284,-1449 1500,-1449 1582,-1367 1582,-1222 1804,-1000 1804,-962.5 1773.5,-932 v1(1718,-932) ; v1(1346,2) 1403,-55 1673,-55 1836,108 v1(2150,108) ; v1(2000,-301) 2101,-301 US1.19
NetUS1_20: US1.20 US7.37 W.12 | length 3613.6
  Top Layer w12: US7.37 260.83,-636.83 v1(279,-655) ; W.12 1253,-1042.37 v1(1253,-1350) ; v1(1761,-982) 1895,-848 2028,-848 2126,-750 2126,-650 2007,-531 v1(2007,-424)
  Bottom Layer w12: v1(279,-655) 449,-655 562,-768 562,-975 669,-1082 1070,-1082 1107.63,-1044.37 1107.63,-1003 W.12 ; v1(1253,-1350) 1438,-1350 1506.13,-1281.87 1506.13,-1236.87 v1(1761,-982) ; v1(2007,-424) 2176,-424 US1.20
NetUS1_21: US1.21 US7.38 W.13 | length 5964.1
  Top Layer w12: v1(124,-651) 124,-675 150,-701 205,-701 235.24,-670.76 US7.38 ; W.13 1160.63,-897 1188.2,-897 1520,-1228.8 1520,-1772 v1(1519,-1773) ; US1.21 2477,23 2477,-667 2505,-695 2618,-695 2673,-750 2673,-916 v1(2637,-952)
  Bottom Layer w12: v1(124,-651) 163,-612 467,-612 599,-744 599,-943 713,-1057 1045.39,-1057 1083.63,-1018.76 1083.63,-927 W.13 ; v1(1519,-1773) 1643,-1649 1825,-1649 1924,-1550 1924,-1243.47 2040.47,-1127 2263,-1127 2438,-952 v1(2637,-952)
NetUS1_22: US1.22 US7.39 W.14 | length 3250.6
  Top Layer w12: US7.39 209.65,-489.35 v1(237,-462) ; W.14 1160.63,-440.37 1200,-401 1200,-272 v1(1599,127)
  Bottom Layer w12: v1(237,-462) 322.75,-547.75 990,-547.75 1055.25,-613 1123.63,-613 1160.63,-650 W.14 ; v1(1599,127) 1617,145 2088,145 2100,157 2185,157 2230,112 2302,112 2315,125 2315,175 2289,201 2224,201 2201,224 2176,224 US1.22
NetUS1_27: US1.27 US7.40 W.4 | length 6225.4
  Top Layer w12: US7.40 184.06,-481 157,-453.94 157,-346 632,129 1408,129 1499,220 1499,280.5 1517.5,299 1601,299 US1.27
  Bottom Layer w12: W.4 1475,-1750 1675,-1550 1871,-1550 1896,-1525 1896,-1222.79 2015.79,-1103 2241,-1103 2697,-647 2697,200 2673,224 2533,224 2458,299 2017.5,299 1999,280.5 1999,220 1980,201 1699,201 US1.27
NetUS1_28: US1.28 US7.41 W.5 | length 6879.3
  Top Layer w12: US7.41 158.46,-608 187,-636.54 v1(187,-658) ; v1(1890.2,-1002.2) 1964,-1076 2180,-1076 2256,-1000 2256,-494 2299,-451 2299,128 v1(2272,155)
  Bottom Layer w12: v1(187,-658) 227.3,-698.3 439.36,-698.3 502,-760.94 502,-1350 484,-1368 430,-1368 380.7,-1318.7 262.8,-1318.7 244,-1337.5 244,-1421 221,-1444 -139,-1444 -182.5,-1487.5 -182.5,-1512.5 -141,-1554 448,-1554 512,-1490 608.18,-1490 706.18,-1588 1098.63,-1588 W.5 1259.63,-1551 1445,-1551 1612.85,-1383.15 1612.85,-1300 1663.85,-1249 1730,-1249 1749,-1230 1749,-1143.4 v1(1890.2,-1002.2) ; US1.28 1631,169 2075.72,169 2106.72,200 2177,200 2222,155 v1(2272,155)
NetUS1_29: US1.29 US7.42 | length 1790.8
  Top Layer w12: US7.42 132.87,-294.63 580.5,153 1353,153 US1.29
NetUS1_30: US1.30 US7.43 | length 1803.6
  Top Layer w12: US7.43 107.28,-236.72 191,-153 191,-62.11 430.11,177 1277,177 US1.30
NetUS7_50: US7.50 X2.1 | length 331.2
  Top Layer w12: X2.1 -236,-550 -228.72,-542.72 US7.50
NetUS7_51: US7.51 X2.2 | length 241.3
  Top Layer w12: X2.2 -307.87,-657.87 US7.51
RB5: CON3.6 R8.2 S.2 US1.38 | length 1063.8
  Top Layer w12: R8.2 515,610 S.2@600,525 ; S.2@850,525 850,500 CON3.6
  Bottom Layer w12: US1.38 599,299 849,299 CON3.6 ; S.2@600,525 S.2@850,525
RB6: CON3.5 US1.39 | length 462.1
  Bottom Layer w12: US1.39 523,323 773,323 CON3.5
RB7: CON3.4 US1.40 | length 462.1
  Bottom Layer w12: US1.40 447,347 697,347 CON3.4
RTS: US1.17 US2.9 | length 4999.1
  Top Layer w12: v1(-131,-1498) -64,-1431 v1(-64,-1226)
  Bottom Layer w12: v1(-131,-1498) 351,-1498 385,-1464 658,-1464 758,-1564 1037,-1564 1044,-1557 1044,-1325 1077,-1292 1311,-1292 1354,-1249 1449,-1249 1661,-1037 1661,-925 1698,-888 1812,-888 1867,-943 2327,-943 2673,-597 2673,-495 2655,-477 2480,-477 2406.5,-550.5 1912,-550.5 1899,-537.5 1899,-401 US1.17 ; v1(-64,-1226) -64,-1175.51 US2.9
RXD: US1.26 US2.12 | length 3609.2
  Top Layer w12: v1(98,-872) 349,-1123 v1(349,-1388) ; v1(1375,-718) 1445,-648 1445,-490 1501,-434 1501,-244 1623,-122 1623,40.88 1750,167.88 US1.26
  Bottom Layer w12: US2.12 64,-1025.51 98,-991.51 v1(98,-872) ; v1(349,-1388) 353,-1392 530,-1392 567,-1355 567,-1200 617,-1150 1207.35,-1150 1264,-1093.35 1264,-775 1321,-718 v1(1375,-718)
SCL: R5.1 US1.18 US4.6 US5.6 US6.14 | length 3234
  Top Layer w12: US4.6 1753,547 1753,312.5 1766.5,299 1880,299 1900,279 1900,-89 2050,-239 US1.18 2050,-525 2150,-625 2150,-776 2126,-800 2126,-1010 v1(2115,-1021)
  Bottom Layer w12: US4.6 1653,647 1997,647 US5.6 R5.1 ; US6.14 1836.83,-1263.17 1836.83,-1197.86 2013.69,-1021 v1(2115,-1021)
SDA: R4.1 US1.23 US4.5 US5.5 US6.15 | length 3268.1
  Top Layer w12: US4.5 1777,623 1777,376 1830,323 1977,323 US1.23 ; US5.5 2203,647 2203,350 2176,323 2123,323 US1.23 ; v1(2175,-989) 2175,-571.68 2101,-497.68 2101,199 US1.23
  Bottom Layer w12: US6.15 1726.04,-1273.96 1755,-1273.96 1773.96,-1255 1773.96,-1226.04 2022,-978 2164,-978 v1(2175,-989) ; R4.1 US5.5
TXD: US1.25 US2.11 | length 3585.3
  Top Layer w12: v1(76,-1151) v1(287,-1362) ; v1(994,-1521) 1106,-1409 1270,-1409 1329,-1350 v1(1329,-1140) ; v1(1381,-830) 1381,-792 1430,-743 1629,-743 1701,-671 1701,-291 1850,-142 US1.25
  Bottom Layer w12: US2.11 0.51,-1075.51 v1(76,-1151) ; v1(287,-1362) 287,-1393.5 329.5,-1436 665,-1436 750,-1521 v1(994,-1521) ; v1(1329,-1140) 1381,-1088 v1(1381,-830)
VCC: C2.1 C3.1 C9.1 C11.2 C12.2 C13.2 C14.2 C15.2 C16.2 C17.2 C22.2 CON3.2 CON8.9 D1.2 D2.2 D3.2 D4.2 D5.2 D7.2 D8.1 PK.2 R4.2 R5.2 R6.2 R7.2 R8.1 R14.1 R17.1 US1.11 US1.32 US2.16 US3.3 US4.8 US5.1 US5.8 US6.16 US7.6 US7.15 US7.16 US7.17 US7.31 US7.32 US7.57 US7.70 US7.89 W.2 | length 25070.8
  Top Layer w12.6: C17.2@-350,-1144.09 -315.91,-1144.09 US7.70 ; v1(-286.58,-780) -255.16,-811.42 US7.57 -115.42,-811.42 v1(-35,-731) ; 90,-1615 132.87,-1572.13 US7.89 132.87,-1450 150.79,-1432.08 384,-1432.08 434.08,-1432.08 ; 388.78,-1230.83 US7.32 US7.31 ; 430,-1272.05 US7.6 ; 489,-1700 489,-1550 489,-1487 ; US7.16 US7.16@539,-1016.14 ; US7.17 539,-990.55 US7.16@539,-1016.14 ; 638.39,-1041.73 US7.15 539,-1041.73 US7.16@539,-1016.14
  Top Layer w35: D3.2 -599,-151 -599,425 -475,549 -389,549 -238,700 D8.1 ; C17.2@-350,-1144.09 C17.2 -320,-1140 -315.91,-1144.09 -307,-1153 v1(-307,-1268) ; v1(-307,-1560) -420,-1673 -420,-2080 C3.1 C2.1 -2,-2250 48,-2200 US3.3 ; C14.2 90,-1615 ; 384,-1432.08 404,-1412.08 404,-1246.05 ; 388.78,-1230.83 404,-1246.05 ; 430,-1272.05 404,-1246.05 ; 434.08,-1432.08 489,-1487 489,-1550 577,-1638 661.07,-1638 717,-1582.07 717,-1351 760,-1308 C15.2 760,-1163.35 638.39,-1041.73 ; R8.1 450,735 480,765 665,765 ; 489,-1700 552,-1763 v1(948,-1763) ; CON3.2 627,323 1002,323 ; US1.32 1077,323 1050,323 1002,323 ; US1.11 R14.1 1350,-600 1252.5,-697.5 1252.5,-851.5 1326,-925 1394.35,-925 1438,-881.35 ; US4.8 1308,608 1062,608 905,765 665,765 ; v1(1830,-600) 1650,-780 1455,-780 1438,-797 1438,-881.35 ; US5.1 US5.8 1915,765 2203,765 2268,700 2268,608 2515,361 2515,-134 v1(2551,-170) ; D7.2 1950,-600 PK.2 ; D4.2 2082,-2050 1915,-1883 1915,-1415 US6.16 1601,-1200 1438,-1037 1438,-881.35 ; 665,765 835,595 880,595 1030,445 1030,351 1002,323
  Bottom Layer w19.2: -143,-780 -97.49,-825.51 US2.16
  Bottom Layer w35: D1.2 D2.2 D3.2 -320,-200 -319,-201 -319,-571 -190,-700 C11.2 ; v1(-307,-1560) v1(-307,-1268) ; v1(-286.58,-780) C11.2 ; -143,-780 C11.2 ; v1(-35,-731) -24,-720 C9.1 60,-525 145.5,-439.5 145.5,-360.5 181,-325 228,-325 265.5,-362.5 265.5,-373.81 391.69,-500 C16.2 ; US3.3 393,-2200 648,-1945 766,-1945 v1(948,-1763) 948,-1900 998,-1950 W.2 1344,-2133.37 1344,-2250 1414,-2320 1830,-2320 CON8.9 2100,-2250 D4.2 D5.2 ; D8.1 264.5,635.5 942,635.5 987.5,590 C22.2 US4.8 1465,765 1785,765 US5.8 ; R17.1 550,100 749,100 762.5,86.5 887.42,86.5 984.42,-10.5 1099.5,-10.5 1160,50 C13.2 1160,175 1150,185 US1.32 ; C12.2 1310,-229 1350,-269 US1.11 ; v1(1830,-600) 1930,-700 PK.2 ; R6.2 R7.2 2441,-60 v1(2551,-170) 2221,-500 D7.2 ; US5.1 1960,510 R5.2 R4.2
pads on no net: CON1.3 CON2.1 CON2.4 CON2.6 CON2.9 CON2.23 CON2.26 CON9.4 CON9.5 CON9.7 CON9.8 CON9.MH1 CON9.MH2 US3. US6.13 US7.1 US7.2 US7.3 US7.4 US7.35 US7.47 US7.48 US7.49 US7.53 US7.54 US7.55 US7.56 US7.60 US7.65 US7.66 US7.67 US7.68 US7.69 US7.71 US7.72 US7.73 US7.74 US7.75 US7.76 US7.77 US7.78 US7.79 US7.80 US7.81 US7.82 US7.84 US7.85 US7.87 US7.88 US7.90 US7.91 US7.92 US7.93 US7.94 US7.95 US7.97 US7.98 US7.99 US7.100 W.

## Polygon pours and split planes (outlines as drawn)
GND on Top Layer (hatched 90Degree grid 10 track 12, remove dead copper): -1100,850 2750,850 2750,-1050 1900,-1050 1900,-2400 -1100,-2400
GND on Bottom Layer (hatched 90Degree grid 10 track 12, remove dead copper): -1100,-2400 1950,-2400 1950,-1150 2750,-1150 2750,850 -1100,850

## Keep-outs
Keep-Out Layer:
  lines w10: 2751.57,-2396.46 2751.57,831.89 -1067.32,831.89 -1067.32,-2396.46 2751.58,-2396.46 ; 2751.57,-1953.54 2751.57,-1914.17 ; 2751.57,408.66 2751.57,448.03

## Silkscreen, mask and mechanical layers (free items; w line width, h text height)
Top Overlay:
  text "Din AN GND" at 2430,-130 h60 r90
  text "PICdemNETNEW KP" at -1031.32,-380 h80 r270
  text "1W GND" at 2440,-560 h50 r90
  text "+  -" at 2450,-1070 h60 r90
  text "+" at -720,-2280 h60 r270
  text "-" at -430,-2330 h60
